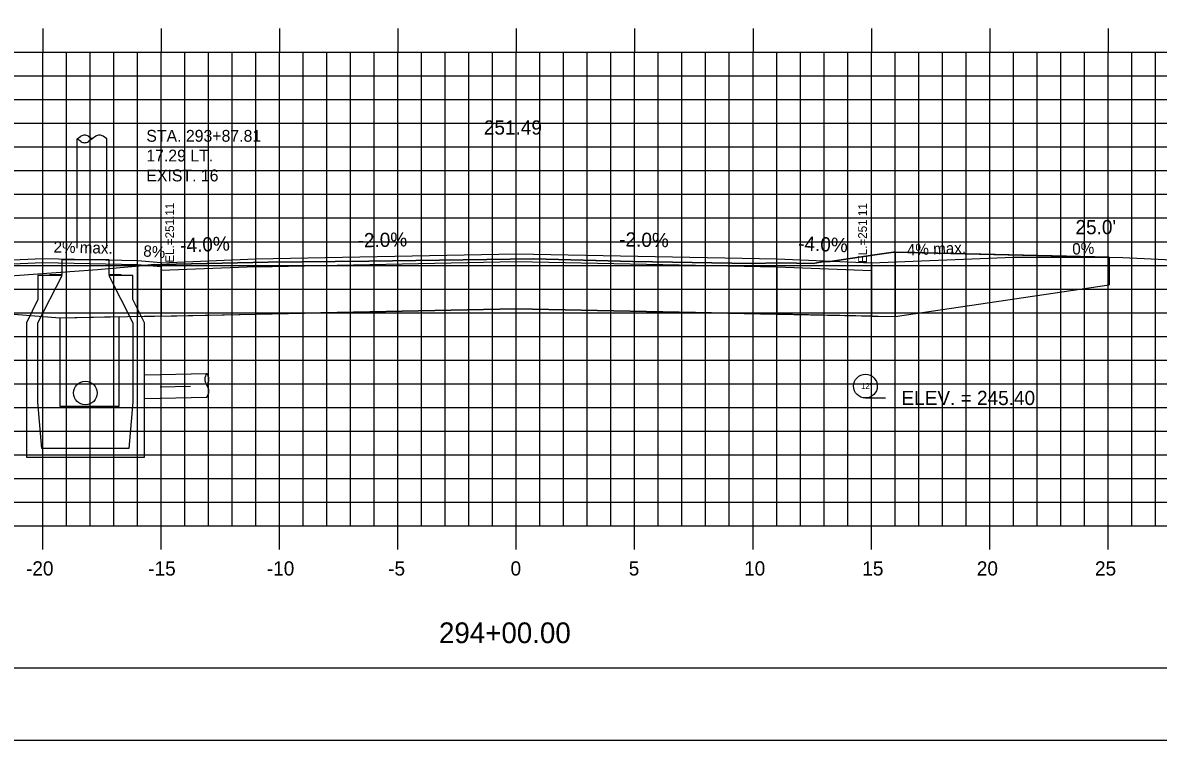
# Model space of a CAD drawing. Extents: x 859129 to 859299, y 366268 to 366378.
# Drawn here: x 859191.61 to 859239.58, y 366268.18 to 366298.48 of the extents above; entities that cross this region are included whole.
import ezdxf

# ---------------------------------------------------------------- set-up
doc = ezdxf.new("R2010")
doc.units = 0
for name, color, linetype in [('ANNOTATION', 7, 'Continuous'), ('BORDER', 7, 'Continuous'), ('D_Drainage_CB_TypeA1-B1', 7, 'Continuous'), ('D_Drainage_Culvert', 7, 'Continuous'), ('D_Roadway_Centerline', 7, 'Continuous'), ('D_Roadway_Centerline_Text', 7, 'Continuous'), ('D_Roadway_Drive_Gravel_LT', 7, 'Continuous'), ('D_Roadway_Drive_Gravel_RT', 7, 'Continuous'), ('D_Roadway_Drive_SubGrade', 7, 'Continuous'), ('D_Roadway_Edge_Shoulder', 7, 'Continuous'), ('D_Roadway_SubGrade', 7, 'Continuous'), ('D_Text_Monospaced', 7, 'Continuous'), ('D_Text_Standard', 7, 'Continuous'), ('H_V ANNOTATION', 7, 'Continuous'), ('JUNK COM EXC', 7, 'Continuous'), ('junk strct exc', 7, 'Continuous'), ('MAJOR', 7, 'Continuous'), ('MINOR', 7, 'Continuous'), ('PDRAIN', 7, 'Continuous'), ('PLOT BOUNDARY', 7, 'Continuous'), ('S_Roadway_Centerline', 7, 'Continuous'), ('S_Utilities_Pole_Power', 7, 'Continuous')]:
    doc.layers.add(name, color=color, linetype=linetype)

msp = doc.modelspace()

# ---------------------------------------------------------------- linework, layer by layer
at = {"layer": 'ANNOTATION'}
msp.add_line((859198.705, 366283.116), (859197.414, 366283.09), dxfattribs=at)
at = {"layer": 'BORDER'}
msp.add_line((859137.462, 366271.236), (859297.462, 366271.236), dxfattribs=at)
at = {"layer": 'D_Drainage_CB_TypeA1-B1'}
for p, q in [((859192.26, 366287.811), (859192.26, 366286.794)), ((859192.26, 366285.81), (859193.277, 366287.811)), ((859193.277, 366287.811), (859192.26, 366287.811)), ((859196.263, 366287.811), (859195.246, 366287.811)), ((859195.246, 366287.811), (859196.263, 366285.81)), ((859196.263, 366286.794), (859196.263, 366287.811)), ((859192.26, 366286.794), (859191.768, 366285.81)), ((859196.755, 366285.81), (859196.263, 366286.794)), ((859191.768, 366285.81), (859191.768, 366280.134)), ((859192.26, 366282.464), (859192.26, 366285.81)), ((859196.263, 366285.81), (859196.263, 366282.464)), ((859196.755, 366280.134), (859196.755, 366285.81)), ((859192.424, 366280.495), (859192.26, 366282.464)), ((859196.263, 366282.464), (859196.099, 366280.495)), ((859196.099, 366280.495), (859192.424, 366280.495)), ((859191.768, 366280.134), (859196.755, 366280.134))]:
    msp.add_line(p, q, dxfattribs=at)
msp.add_lwpolyline([(859192.752, 366287.853), (859193.277, 366287.853), (859193.277, 366288.476), (859195.246, 366288.476), (859195.246, 366287.853), (859195.771, 366287.853)], dxfattribs=at)
at = {"layer": 'D_Drainage_Culvert'}
for p, q in [((859196.755, 366283.617), (859199.392, 366283.67)), ((859196.755, 366282.616), (859199.392, 366282.67))]:
    msp.add_line(p, q, dxfattribs=at)
for centre, start, end in [((859199.725, 366283.42), 143.1301, 216.8699), ((859199.058, 366283.42), 323.1301, 36.8699), ((859199.058, 366282.92), 323.1301, 36.8699)]:
    msp.add_arc(centre, 0.417, start, end, dxfattribs=at)
at = {"layer": 'D_Roadway_Centerline'}
msp.add_lwpolyline([(859201.462, 366288.506), (859212.462, 366288.726), (859223.462, 366288.506)], dxfattribs=at)
at = {"layer": 'D_Roadway_Drive_Gravel_LT'}
for p, q in [((859192.462, 366288.506), (859189.457, 366288.386)), ((859196.462, 366288.426), (859192.462, 366288.506)), ((859197.462, 366288.346), (859196.462, 366288.426)), ((859192.468, 366288.339), (859189.457, 366288.219)), ((859196.453, 366288.259), (859192.454, 366288.339)), ((859197.457, 366288.179), (859196.453, 366288.259)), ((859197.462, 366288.346), (859197.462, 366288.013))]:
    msp.add_line(p, q, dxfattribs=at)
at = {"layer": 'D_Roadway_Drive_Gravel_RT'}
for p in [(859227.462, 366288.346), (859233.462, 366288.586)]:
    msp.add_line(p, (859233.462, 366288.586), dxfattribs=at)
at = {"layer": 'D_Roadway_Drive_SubGrade'}
for p, q in [((859233.462, 366288.586), (859237.508, 366288.586)), ((859237.508, 366288.586), (859237.508, 366287.419)), ((859228.462, 366286.073), (859237.508, 366287.419)), ((859193.184, 366286.007), (859184.557, 366286.673)), ((859197.457, 366286.092), (859193.184, 366286.007)), ((859227.462, 366286.093), (859228.462, 366286.073))]:
    msp.add_line(p, q, dxfattribs=at)
at = {"layer": 'D_Roadway_Edge_Shoulder'}
msp.add_line((859227.462, 366288.346), (859227.462, 366288.013), dxfattribs=at)
msp.add_lwpolyline([(859197.462, 366288.346), (859201.462, 366288.506), (859212.462, 366288.726), (859223.462, 366288.506), (859227.462, 366288.346)], dxfattribs=at)
at = {"layer": 'D_Roadway_SubGrade'}
for points in [[(859201.462, 366286.173), (859201.462, 366288.173), (859212.462, 366288.393), (859223.462, 366288.173), (859223.462, 366286.173), (859212.462, 366286.393)], [(859201.462, 366288.173), (859197.462, 366288.013), (859197.462, 366286.093), (859201.462, 366286.173)], [(859223.462, 366288.173), (859227.462, 366288.013), (859227.462, 366286.093), (859223.462, 366286.173)]]:
    msp.add_lwpolyline(points, close=True, dxfattribs=at)
at = {"layer": 'D_Text_Standard'}
msp.add_lwpolyline([(859227.212, 366282.636), (859227.374, 366282.636), (859228.054, 366282.636)], dxfattribs=at)
at = {"layer": 'JUNK COM EXC'}
for points in [[(859228.461, 366288.792), (859228.402, 366288.793), (859227.504, 366288.671), (859225.72, 366288.403), (859225.461, 366288.398), (859225, 366288.313), (859223.589, 366288.339), (859222.394, 366288.312), (859217.392, 366288.393), (859213.208, 366288.504), (859206.239, 366288.411), (859201.989, 366288.376), (859198.102, 366288.284), (859197.292, 366288.264), (859197.182, 366288.265), (859196.457, 366288.204), (859196.457, 366286.072), (859201.462, 366286.173), (859212.462, 366286.393), (859223.462, 366286.173), (859228.461, 366286.073), (859228.461, 366288.792)], [(859228.462, 366288.792), (859228.462, 366286.073), (859228.462, 366286.073), (859237.508, 366287.419), (859237.508, 366288.586), (859228.462, 366288.792)]]:
    msp.add_lwpolyline(points, dxfattribs=at)
at = {"layer": 'junk strct exc'}
msp.add_lwpolyline([(859193.184, 366286.007), (859193.184, 366282.286), (859195.684, 366282.286), (859195.684, 366286.057)], close=True, dxfattribs=at)
at = {"layer": 'MAJOR'}
for p, q in [((859192.462, 366298.238), (859192.462, 366297.236)), ((859197.462, 366298.238), (859197.462, 366297.236)), ((859202.462, 366298.238), (859202.462, 366297.236)), ((859207.462, 366298.238), (859207.462, 366297.236)), ((859212.462, 366298.238), (859212.462, 366297.236)), ((859217.462, 366298.238), (859217.462, 366297.236)), ((859222.462, 366298.238), (859222.462, 366297.236)), ((859227.462, 366298.238), (859227.462, 366297.236)), ((859232.462, 366298.238), (859232.462, 366297.236)), ((859237.462, 366298.238), (859237.462, 366297.236)), ((859142.462, 366297.236), (859282.462, 366297.236)), ((859142.462, 366297.236), (859282.462, 366297.236)), ((859192.462, 366277.236), (859192.462, 366297.236)), ((859197.462, 366277.236), (859197.462, 366297.236)), ((859202.462, 366277.236), (859202.462, 366297.236)), ((859207.462, 366277.236), (859207.462, 366297.236)), ((859212.462, 366277.236), (859212.462, 366297.236)), ((859217.462, 366277.236), (859217.462, 366297.236)), ((859222.462, 366277.236), (859222.462, 366297.236)), ((859227.462, 366277.236), (859227.462, 366297.236)), ((859232.462, 366277.236), (859232.462, 366297.236)), ((859237.462, 366277.236), (859237.462, 366297.236)), ((859142.462, 366292.236), (859282.462, 366292.236)), ((859142.462, 366287.236), (859282.462, 366287.236)), ((859142.462, 366282.236), (859282.462, 366282.236)), ((859142.462, 366277.236), (859282.462, 366277.236)), ((859142.462, 366277.236), (859282.462, 366277.236)), ((859192.462, 366276.234), (859192.462, 366277.236)), ((859197.462, 366276.234), (859197.462, 366277.236)), ((859202.462, 366276.234), (859202.462, 366277.236)), ((859207.462, 366276.234), (859207.462, 366277.236)), ((859212.462, 366276.234), (859212.462, 366277.236)), ((859217.462, 366276.234), (859217.462, 366277.236)), ((859222.462, 366276.234), (859222.462, 366277.236)), ((859227.462, 366276.234), (859227.462, 366277.236)), ((859232.462, 366276.234), (859232.462, 366277.236)), ((859237.462, 366276.234), (859237.462, 366277.236))]:
    msp.add_line(p, q, dxfattribs=at)
at = {"layer": 'MINOR'}
for p, q in [((859193.462, 366277.236), (859193.462, 366297.236)), ((859194.462, 366277.236), (859194.462, 366297.236)), ((859195.462, 366277.236), (859195.462, 366297.236)), ((859196.462, 366277.236), (859196.462, 366297.236)), ((859198.462, 366277.236), (859198.462, 366297.236)), ((859199.462, 366277.236), (859199.462, 366297.236)), ((859200.462, 366277.236), (859200.462, 366297.236)), ((859201.462, 366277.236), (859201.462, 366297.236)), ((859203.462, 366277.236), (859203.462, 366297.236)), ((859204.462, 366277.236), (859204.462, 366297.236)), ((859205.462, 366277.236), (859205.462, 366297.236)), ((859206.462, 366277.236), (859206.462, 366297.236)), ((859208.462, 366277.236), (859208.462, 366297.236)), ((859209.462, 366277.236), (859209.462, 366297.236)), ((859210.462, 366277.236), (859210.462, 366297.236)), ((859211.462, 366277.236), (859211.462, 366297.236)), ((859213.462, 366277.236), (859213.462, 366297.236)), ((859214.462, 366277.236), (859214.462, 366297.236)), ((859215.462, 366277.236), (859215.462, 366297.236)), ((859216.462, 366277.236), (859216.462, 366297.236)), ((859218.462, 366277.236), (859218.462, 366297.236)), ((859219.462, 366277.236), (859219.462, 366297.236)), ((859220.462, 366277.236), (859220.462, 366297.236)), ((859221.462, 366277.236), (859221.462, 366297.236)), ((859223.462, 366277.236), (859223.462, 366297.236)), ((859224.462, 366277.236), (859224.462, 366297.236)), ((859225.462, 366277.236), (859225.462, 366297.236)), ((859226.462, 366277.236), (859226.462, 366297.236)), ((859228.462, 366277.236), (859228.462, 366297.236)), ((859229.462, 366277.236), (859229.462, 366297.236)), ((859230.462, 366277.236), (859230.462, 366297.236)), ((859231.462, 366277.236), (859231.462, 366297.236)), ((859233.462, 366277.236), (859233.462, 366297.236)), ((859234.462, 366277.236), (859234.462, 366297.236)), ((859235.462, 366277.236), (859235.462, 366297.236)), ((859236.462, 366277.236), (859236.462, 366297.236)), ((859238.462, 366277.236), (859238.462, 366297.236)), ((859239.462, 366277.236), (859239.462, 366297.236)), ((859142.462, 366296.236), (859282.462, 366296.236)), ((859142.462, 366295.236), (859282.462, 366295.236)), ((859142.462, 366294.236), (859282.462, 366294.236)), ((859142.462, 366293.236), (859282.462, 366293.236)), ((859142.462, 366291.236), (859282.462, 366291.236)), ((859142.462, 366290.236), (859282.462, 366290.236)), ((859142.462, 366289.236), (859282.462, 366289.236)), ((859142.462, 366288.236), (859282.462, 366288.236)), ((859142.462, 366286.236), (859282.462, 366286.236)), ((859142.462, 366285.236), (859282.462, 366285.236)), ((859142.462, 366284.236), (859282.462, 366284.236)), ((859142.462, 366283.236), (859282.462, 366283.236)), ((859142.462, 366281.236), (859282.462, 366281.236)), ((859142.462, 366280.236), (859282.462, 366280.236)), ((859142.462, 366279.236), (859282.462, 366279.236)), ((859142.462, 366278.236), (859282.462, 366278.236))]:
    msp.add_line(p, q, dxfattribs=at)
at = {"layer": 'PDRAIN'}
for centre in [(859227.212, 366283.136), (859194.262, 366282.846)]:
    msp.add_circle(centre, 0.5, dxfattribs=at)
at = {"layer": 'PLOT BOUNDARY'}
msp.add_lwpolyline([(859129.368, 366268.177), (859299.368, 366268.177), (859299.368, 366378.177), (859129.368, 366378.177)], close=True, dxfattribs=at)
at = {"layer": 'S_Roadway_Centerline'}
msp.add_lwpolyline([(859169.906, 366286.981), (859171.66, 366286.936), (859172.507, 366286.988), (859185.297, 366287.368), (859188.748, 366287.629), (859194.777, 366288.061), (859197.182, 366288.265), (859197.292, 366288.264), (859198.102, 366288.284), (859201.989, 366288.376), (859206.239, 366288.411), (859213.208, 366288.504), (859217.392, 366288.393), (859222.394, 366288.312), (859223.589, 366288.339), (859225, 366288.313), (859225.461, 366288.398), (859225.72, 366288.403), (859227.504, 366288.671), (859228.402, 366288.793), (859238.08, 366288.573), (859248.539, 366288.071), (859258.988, 366287.239), (859264.658, 366286.917)], dxfattribs=at)
at = {"layer": 'S_Utilities_Pole_Power'}
for p, q in [((859193.919, 366293.577), (859194.075, 366293.687)), ((859194.388, 366293.687), (859194.544, 366293.577)), ((859194.701, 366293.687), (859194.544, 366293.577)), ((859195.169, 366293.577), (859195.013, 366293.687)), ((859193.919, 366288.958), (859193.922, 366293.577)), ((859194.075, 366293.466), (859193.919, 366293.577)), ((859194.544, 366293.577), (859194.388, 366293.466)), ((859195.169, 366288.958), (859195.172, 366293.577))]:
    msp.add_line(p, q, dxfattribs=at)
for centre, start, end in [((859194.232, 366293.466), 90, 125.2644), ((859194.232, 366293.466), 54.7356, 90), ((859194.857, 366293.466), 90, 125.2644), ((859194.857, 366293.466), 54.7356, 90), ((859194.232, 366293.687), 234.7356, 270), ((859194.232, 366293.687), 270, 305.2644)]:
    msp.add_arc(centre, 0.271, start, end, dxfattribs=at)

# ---------------------------------------------------------------- texts
at = {"layer": 'ANNOTATION'}
for s, rotation, p in [('-4.0%', 2.2906, (859198.278, 366288.779)), ('-2.0%', 1.1458, (859205.765, 366288.992)), ('-2.0%', 358.8542, (859216.805, 366289.039)), ('-4.0%', 357.7095, (859224.359, 366288.87))]:
    msp.add_text(s, height=0.6, rotation=rotation, dxfattribs=at).set_placement(p)
at = {"layer": 'D_Roadway_Centerline_Text'}
msp.add_text('251.49', height=0.6, dxfattribs=at).set_placement((859211.092, 366293.758))
at = {"layer": 'D_Roadway_Drive_Gravel_LT'}
for s, rotation, p in [('2% max.', 358.8078, (859192.915, 366288.776)), ('8%', 355.4261, (859196.692, 366288.613))]:
    msp.add_text(s, height=0.48, rotation=rotation, dxfattribs=at).set_placement(p)
at = {"layer": 'D_Roadway_Drive_Gravel_RT'}
for s, p in [('4% max.', (859228.974, 366288.647)), ('0%', (859235.957, 366288.687))]:
    msp.add_text(s, height=0.48, rotation=2.2906, dxfattribs=at).set_placement(p)
at = {"layer": 'D_Text_Monospaced'}
for s, height, p in [('STA. 293+87.81', 0.49998, (859196.836, 366293.456)), ('17.29 LT.', 0.5, (859196.836, 366292.622)), ('EXIST. 16', 0.5, (859196.836, 366291.782))]:
    msp.add_text(s, height=height, dxfattribs=at).set_placement(p)
at = {"layer": 'D_Text_Standard'}
for p in [(859198.005, 366288.21), (859227.273, 366288.192)]:
    msp.add_text(' EL.=251.11', height=0.36848, rotation=90, dxfattribs=at).set_placement(p)
for s, p in [("25.0'", (859236.084, 366289.551)), ('ELEV. = 245.40', (859228.734, 366282.336))]:
    msp.add_text(s, height=0.6, dxfattribs=at).set_placement(p)
at = {"layer": 'H_V ANNOTATION'}
for s, height, p in [('-20', 0.6, (859191.755, 366275.136)), ('-15', 0.6, (859196.918, 366275.136)), ('-10', 0.6, (859201.927, 366275.136)), ('-5', 0.6, (859207.052, 366275.136)), ('0', 0.6, (859212.221, 366275.136)), ('5', 0.6, (859217.213, 366275.136)), ('10', 0.6, (859222.087, 366275.136)), ('15', 0.6, (859227.079, 366275.136)), ('20', 0.6, (859231.916, 366275.136)), ('25', 0.6, (859236.908, 366275.136)), ('294+00.00', 0.875, (859209.2, 366272.28))]:
    msp.add_text(s, height=height, dxfattribs=at).set_placement(p)
at = {"layer": 'PDRAIN'}
msp.add_text('12"', height=0.25, dxfattribs=at).set_placement((859227.021, 366283.012))
at = {"layer": 'S_Roadway_Centerline'}
for s, p in [('C', (859213.202, 366288.504)), ('L', (859213.208, 366288.496))]:
    msp.add_text(s, height=0.0146, dxfattribs=at).set_placement(p)

doc.saveas('drawing.dxf')
